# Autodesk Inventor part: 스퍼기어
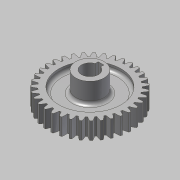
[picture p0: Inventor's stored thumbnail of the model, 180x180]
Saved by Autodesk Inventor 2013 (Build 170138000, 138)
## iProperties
Created: 2013-08
Part Number: 스퍼기어
Material: 강
Document SubType Name: Modeling
Designer: 한국산업디자인학원
Categories: <?xml version="1.0" encoding="UTF-16"?> <MemberInstance><Categories><FamilyTemplate><FamilyTemplateParameter ValueType="xs:double" Id="1" ObjectReferenceKey="da
Density: 1 g/cm^3
CustomPartVersion: 1
Author: 한국산업디자인학원
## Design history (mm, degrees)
sketch "Sketch1"
  geometry: C1 r 37 at (0, 0)
  constraints: 1 centre point
  dimensions: "d0" = 74 diameter of C1 (= da_da)
extrude "Extrusion1" new body sketch "Sketch1" distance "d1" = 15 (= da_b); taper "d2" = 0 deg
workplane "Work Plane2"
feature "피치 지름" dims "d4" = 10, "d5" = 0
workplane "Work Plane8"
workplane "Work Plane9"
feature "스퍼 기어" dims "da_b" = 15, "da_d" = 70, "da_aw" = 70, "da_da" = 74, "da_df" = 65, "da_dw" = 70, angle "da_beta" = 0 deg, "da_lefttooth" = 0, "da_righttooth" = 0
sketch "스케치3"
  geometry: C1 r 12.5 at (0, 0); A1 r 37 centre (0, 0) between (-5.788, 36.544) and (-7.422, 36.248) reference
  constraints: 1 centre point, 1 coincident
  dimensions: "d49" = 25 diameter of C1
extrude "돌출2" join sketch "스케치3" distance "d51" = 13; taper "d52" = 0 deg
sketch "스케치4"
  geometry: C1 r 12.5 at (0, 0); A1 r 32.5 centre (0, 0) between (9.347, 31.127) and (7.941, 31.515) reference
  constraints: 1 centre point, 1 coincident
  dimensions: "d53" = 25 diameter of C1
extrude "돌출3" join sketch "스케치4" distance "d54" = 3; taper "d55" = 0 deg
sketch "스케치5"
  geometry: L1 (0, 0)-(0, 9.8); L2 (0, 9.8)-(2.5, 9.8); L3 (2.5, 9.8)-(2.5, 7.071); L4 (0, 9.8)-(-2.5, 9.8); L5 (-2.5, 9.8)-(-2.5, 7.071); C1 r 12.5 at (0, 0) reference; A1 r 7.5 centre (0, 0) between (-2.5, 7.071) and (2.5, 7.071)
  constraints: 10 end point, 4 perpendicular, 2 point on circle, 1 centre point, 1 coincident, 1 vertical
  dimensions: "d56" = 15 diameter of A1; "d57" = 9.8 distance of L1.start L1.end; "d58" = 2.5 distance of L1.end L2.end; "d59" = 2.5 distance of L1.end L4.end
extrude "돌출4" cut sketch "스케치5" stored distance "d60" = 3; taper "d61" = 0 deg
sketch "스케치7"
  geometry: C1 r 12.5 at (0, 0) reference; C2 r 12.5 at (0, 0); C3 r 27.5 at (0, 0); A1 r 37 centre (0, 0) between (-5.788, 36.544) and (-7.422, 36.248) reference
  constraints: 2 centre point, 2 coincident, 1 concentric
  dimensions: "d62" = 55 diameter of C3
extrude "돌출5" cut sketch "스케치7" distance "d63" = 5; taper "d64" = 0 deg
fillet "모깎기1" dims "d65" = 3
body "Solid1"
mirror "대칭1"
sketch "Sketch2"
  geometry: C1 r 37 at (0, 0) reference; C2 r 35 at (0, 0)
  constraints: 1 centre point, 1 coincident
  dimensions: "d3" = 70 diameter of C2 (= da_dw)
body "Srf1"
other parameters: "d17" = 0, "d34" = 0.8976 (computed from da_z), "d39" = 0, "d41" = 0, "d47" = 0, "d48" = 0
